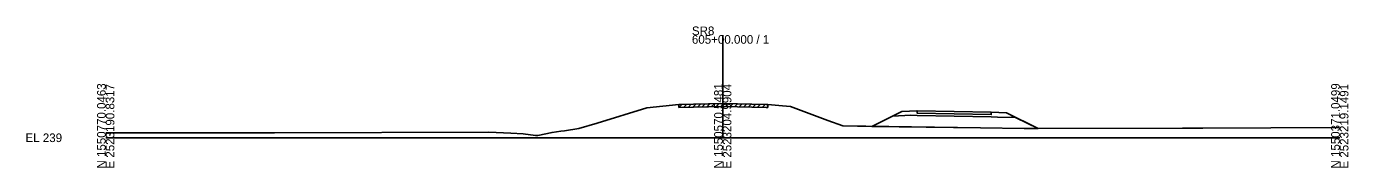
# Model space of a CAD drawing. Extents: x -26 to 2803, y -10 to 19537.
# Drawn here: x -25.7 to 402.8, y 11990.3 to 12036.2 of the extents above; entities that cross this region are included whole.
import ezdxf

# ---------------------------------------------------------------- set-up
doc = ezdxf.new("R2010")
doc.units = 0
for name, color, linetype in [('50', 7, 'Continuous'), ('XS_CELL', 7, 'Continuous'), ('XS_M_MULTI', 7, 'Continuous'), ('XS_M_SHAPES_EARTHWORK', 7, 'Continuous'), ('XS_P_FINISHED_GRADE', 7, 'Continuous'), ('XS_P_SUBGRADE_GRANULAR', 7, 'Continuous'), ('XS_P_SUBGRADE_PAVEMENT', 7, 'Continuous'), ('XS_X_GROUND', 7, 'Continuous')]:
    doc.layers.add(name, color=color, linetype=linetype)

msp = doc.modelspace()

# ---------------------------------------------------------------- linework, layer by layer
at = {"layer": '50'}
for p, q in [((185.77, 12009.8), (186.79, 12010.82)), ((185.77, 12009.8), (185.77, 12010.8)), ((185.77, 12009.8), (200.14, 12010.11)), ((187.27, 12009.83), (188.29, 12010.85)), ((188.77, 12009.86), (189.79, 12010.88)), ((190.27, 12009.9), (191.29, 12010.92)), ((191.77, 12009.93), (192.79, 12010.95)), ((193.27, 12009.96), (194.29, 12010.98)), ((194.77, 12009.99), (195.79, 12011.02)), ((196.27, 12010.03), (197.29, 12011.05)), ((197.77, 12010.06), (198.79, 12011.08)), ((199.27, 12010.09), (200.29, 12011.11)), ((200.14, 12010.11), (214.06, 12009.83)), ((200.77, 12010.1), (201.75, 12011.08)), ((202.27, 12010.07), (203.25, 12011.05)), ((203.77, 12010.04), (204.75, 12011.02)), ((205.27, 12010.01), (206.25, 12010.99)), ((206.77, 12009.98), (207.75, 12010.96)), ((208.27, 12009.95), (209.25, 12010.93)), ((209.77, 12009.92), (210.75, 12010.9)), ((211.27, 12009.89), (212.25, 12010.87)), ((212.77, 12009.86), (213.75, 12010.84)), ((214.06, 12009.83), (214.59, 12009.82)), ((214.59, 12010.82), (214.59, 12009.82))]:
    msp.add_line(p, q, dxfattribs=at)
at = {"layer": 'XS_CELL'}
for p, q in [((200, 12000), (200, 12033.34)), ((0, 12000), (200, 12000)), ((200, 12000), (400, 12000))]:
    msp.add_line(p, q, dxfattribs=at)
at = {"layer": 'XS_M_MULTI'}
for p, q in [((248.29, 12003.7), (258, 12008.55)), ((258, 12008.55), (263, 12008.75)), ((263, 12008.75), (275, 12008.51)), ((275, 12008.51), (287, 12008.27)), ((287, 12008.27), (292, 12008.07)), ((292, 12008.07), (302.19, 12002.98))]:
    msp.add_line(p, q, dxfattribs=at)
for points in [[(0.02, 12001.57), (2.38, 12001.57), (5.53, 12001.58), (44.07, 12001.62), (45.33, 12001.63), (48.48, 12001.63), (49.05, 12001.63), (54.75, 12001.65), (124.19, 12001.83), (131.36, 12001.5), (135.3, 12001.33), (139.27, 12000.74), (140.08, 12000.79), (144.66, 12001.73), (147.56, 12002.14), (148.66, 12002.3), (153.33, 12002.96), (159.28, 12004.79), (175.34, 12009.75), (185.77, 12010.8), (200.14, 12011.11), (214.06, 12010.83), (214.59, 12010.82), (219.37, 12010.41), (221.92, 12010.2), (234.11, 12005.62), (238.87, 12003.83), (248.29, 12003.7)], [(302.19, 12002.98), (349.02, 12003.11), (350.7, 12003.11), (351.94, 12003.11), (352.35, 12003.12), (353.16, 12003.12), (355.62, 12003.13), (399.74, 12003.37)]]:
    msp.add_lwpolyline(points, dxfattribs=at)
at = {"layer": 'XS_M_SHAPES_EARTHWORK'}
for points in [[(289, 12006.73), (294.92, 12006.62), (292, 12008.07), (287, 12008.27), (287, 12007.52), (275, 12007.76), (263, 12008), (263, 12008.75), (258, 12008.55), (255, 12007.05), (261, 12007.29), (263, 12007.25), (275, 12007.01), (287, 12006.77)], [(275, 12008.51), (287, 12008.27), (287, 12007.52), (275, 12007.76), (263, 12008), (263, 12008.75)], [(248.29, 12003.7), (283.56, 12003.2), (297.7, 12003), (299.18, 12002.97), (302.19, 12002.98), (294.92, 12006.62), (289, 12006.73), (287, 12006.77), (275, 12007.01), (263, 12007.25), (261, 12007.29), (255, 12007.05)]]:
    msp.add_lwpolyline(points, close=True, dxfattribs=at)
at = {"layer": 'XS_P_FINISHED_GRADE'}
for p, q in [((258, 12008.55), (248.29, 12003.7)), ((263, 12008.75), (258, 12008.55)), ((263, 12008.75), (275, 12008.51)), ((275, 12008.51), (287, 12008.27)), ((287, 12008.27), (292, 12008.07)), ((292, 12008.07), (302.19, 12002.98))]:
    msp.add_line(p, q, dxfattribs=at)
at = {"layer": 'XS_P_SUBGRADE_GRANULAR'}
for p, q in [((261, 12007.29), (255, 12007.05)), ((263, 12007.25), (261, 12007.29)), ((263, 12007.25), (275, 12007.01)), ((275, 12007.01), (287, 12006.77)), ((287, 12006.77), (289, 12006.73)), ((289, 12006.73), (294.92, 12006.62))]:
    msp.add_line(p, q, dxfattribs=at)
at = {"layer": 'XS_P_SUBGRADE_PAVEMENT'}
for p, q in [((263, 12008), (263, 12008.75)), ((263, 12008), (275, 12007.76)), ((275, 12007.76), (287, 12007.52)), ((287, 12007.52), (287, 12008.27))]:
    msp.add_line(p, q, dxfattribs=at)
at = {"layer": 'XS_X_GROUND'}
msp.add_lwpolyline([(0.02, 12001.57), (2.38, 12001.57), (5.53, 12001.58), (44.07, 12001.62), (45.33, 12001.63), (48.48, 12001.63), (49.05, 12001.63), (54.75, 12001.65), (124.19, 12001.83), (131.36, 12001.5), (135.3, 12001.33), (139.27, 12000.74), (140.08, 12000.79), (144.66, 12001.73), (147.56, 12002.14), (148.66, 12002.3), (153.33, 12002.96), (159.28, 12004.79), (175.34, 12009.75), (185.77, 12010.8), (200.14, 12011.11), (214.06, 12010.83), (214.59, 12010.82), (219.37, 12010.41), (221.92, 12010.2), (234.11, 12005.62), (238.87, 12003.83), (283.56, 12003.2), (297.7, 12003), (299.18, 12002.97), (349.02, 12003.11), (350.7, 12003.11), (351.94, 12003.11), (352.35, 12003.12), (353.16, 12003.12), (355.62, 12003.13), (399.74, 12003.37)], dxfattribs=at)

# ---------------------------------------------------------------- texts
at = {"layer": 'XS_CELL'}
for s, p in [('SR8', (190, 12033.34)), ('605+00.000 / 1', (190, 12030.54)), ('EL 239', (-26, 11998.6))]:
    msp.add_text(s, height=2.8, dxfattribs=at).set_placement(p)
for s, p in [('N 1550770.0463', (0, 11990)), ('E 2523190.8317', (2.8, 11990)), ('N 1550570.5481', (200, 11990)), ('E 2523204.9904', (202.8, 11990)), ('N 1550371.0499', (400, 11990)), ('E 2523219.1491', (402.8, 11990))]:
    msp.add_text(s, height=2.8, rotation=90, dxfattribs=at).set_placement(p)

doc.saveas('drawing.dxf')
